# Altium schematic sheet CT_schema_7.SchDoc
size 371 x 245 mm
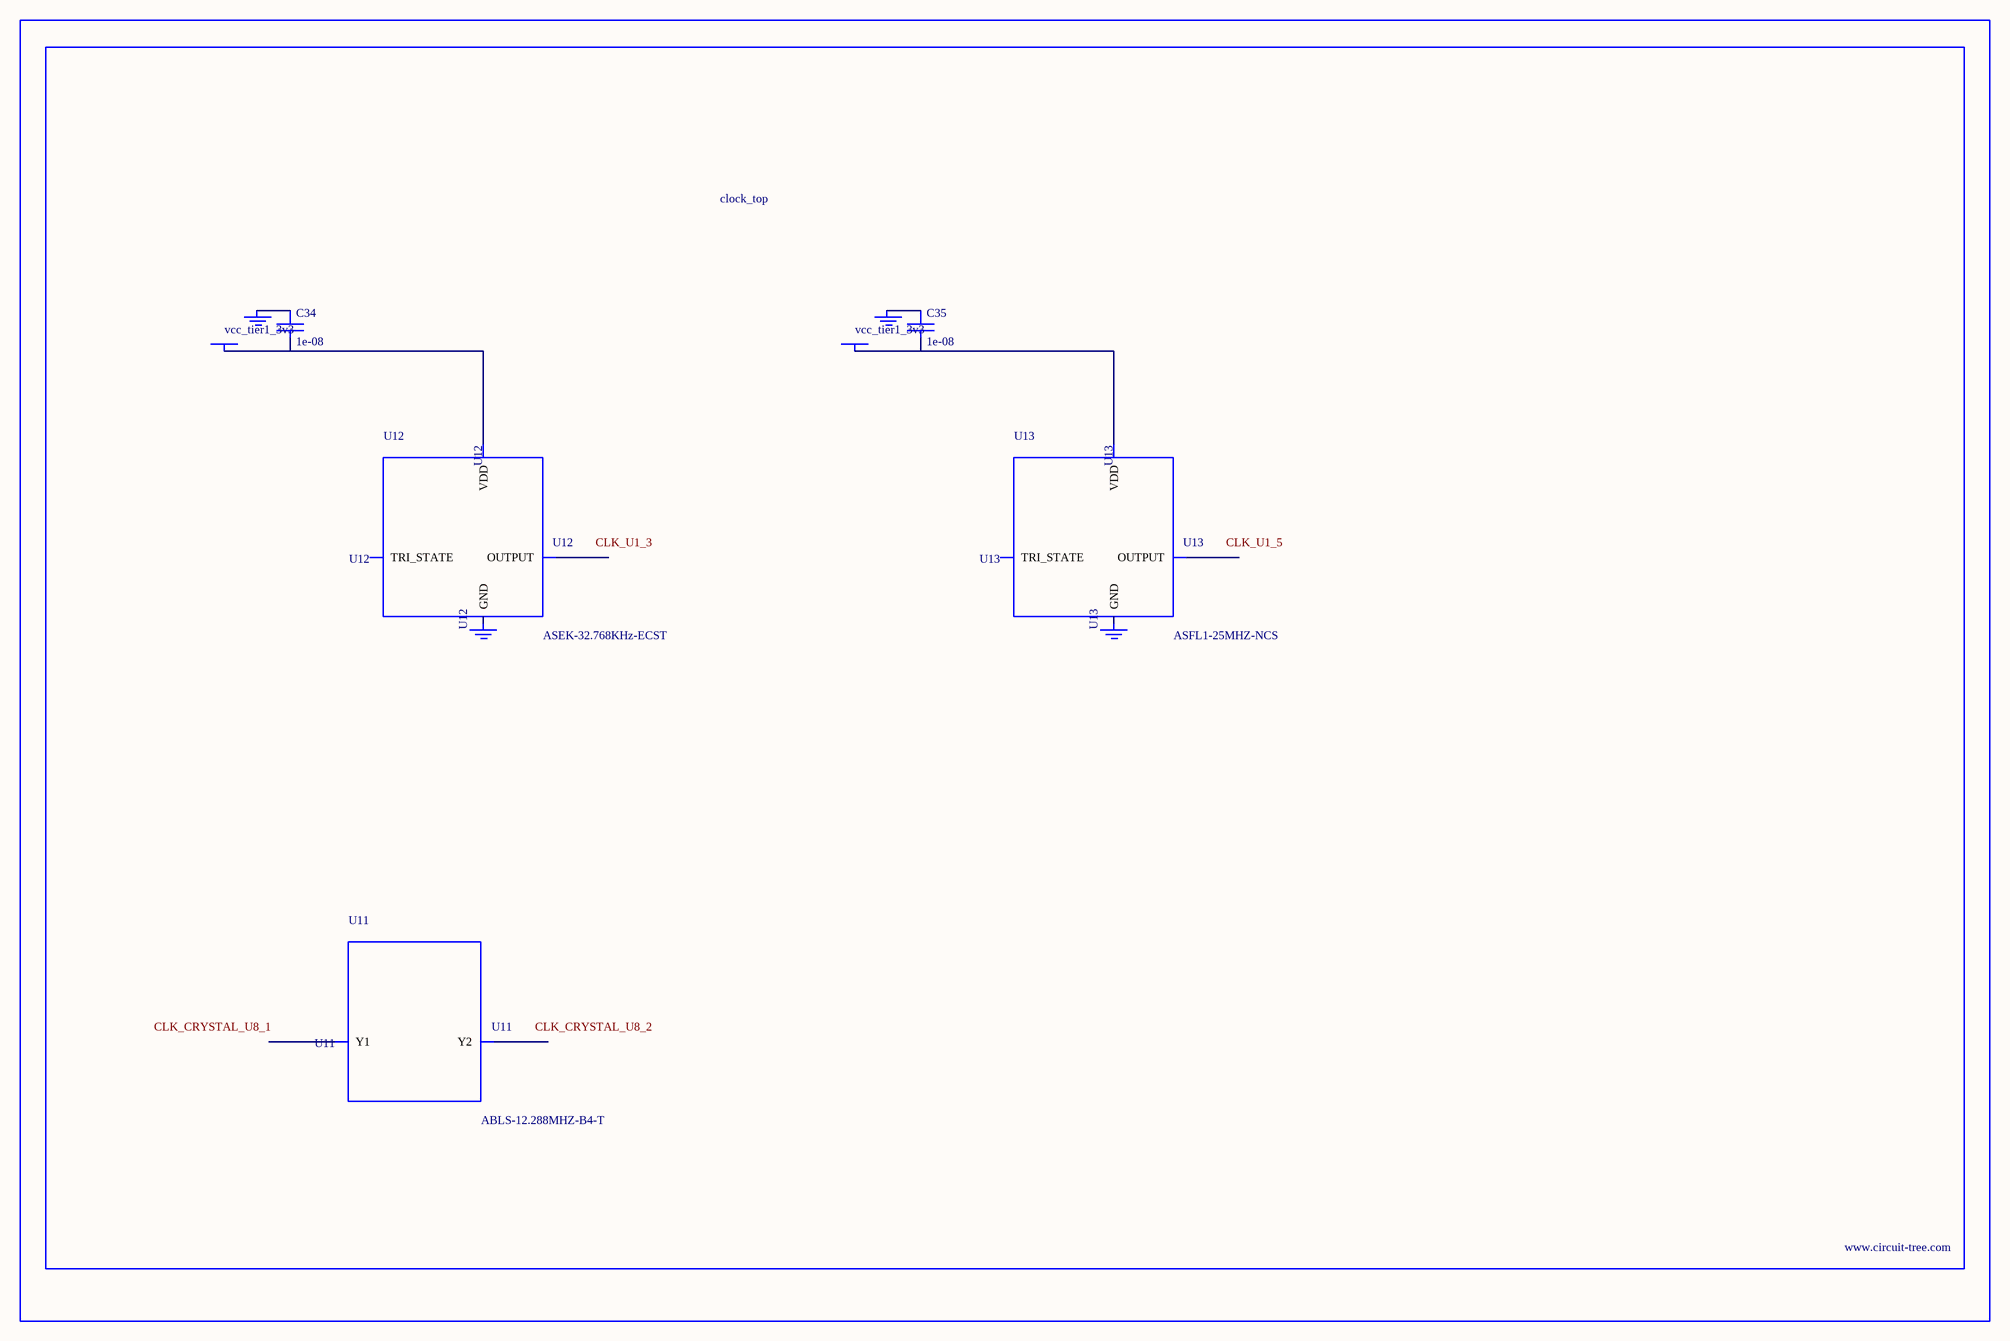
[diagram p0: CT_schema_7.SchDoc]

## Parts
BORDER6  (no value)
C34  1e-08  [C0402]
C35  1e-08  [C0402]
GND_INSTANCE_6_0  (no value)
GND_INSTANCE_6_1  (no value)
GND_INSTANCE_6_2  (no value)
GND_INSTANCE_6_3  (no value)
POWER_INSTANCE_6_0  vcc_tier1_3v3
POWER_INSTANCE_6_1  vcc_tier1_3v3
U11  ABLS-12.288MHZ-B4-T  [ABLS-12.288MHZ-B4-T]
U12  ASEK-32.768KHz-ECST  [ASEK]
U13  ASFL1-25MHZ-NCS  [ASFL1]

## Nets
NetC34_1: C34.1 GND_INSTANCE_6_0.0(GND)
NetC34_2: C34.2 POWER_INSTANCE_6_0.0(PWR) U12.4(VDD)
NetC35_1: C35.1 GND_INSTANCE_6_2.0(GND)
NetC35_2: C35.2 POWER_INSTANCE_6_1.0(PWR) U13.4(VDD)

Not connected (* = marked no-connect by the designer): GND_INSTANCE_6_1 0(GND); GND_INSTANCE_6_3 0(GND); U11 1(Y1) 2(Y2); U12 1(TRI_STATE) 2(GND) 3(OUTPUT); U13 1(TRI_STATE) 2(GND) 3(OUTPUT)

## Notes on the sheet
- Labels drawn without touching a wire or pin: CLK_CRYSTAL_U8_1, CLK_CRYSTAL_U8_2, CLK_U1_3, CLK_U1_5

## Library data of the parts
BORDER6 = BORDER_PAGE6
C34 C35 = C0402C103K3RAC
GND_INSTANCE_6_0-GND_INSTANCE_6_3 = GND
POWER_INSTANCE_6_0 POWER_INSTANCE_6_1 = PWR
